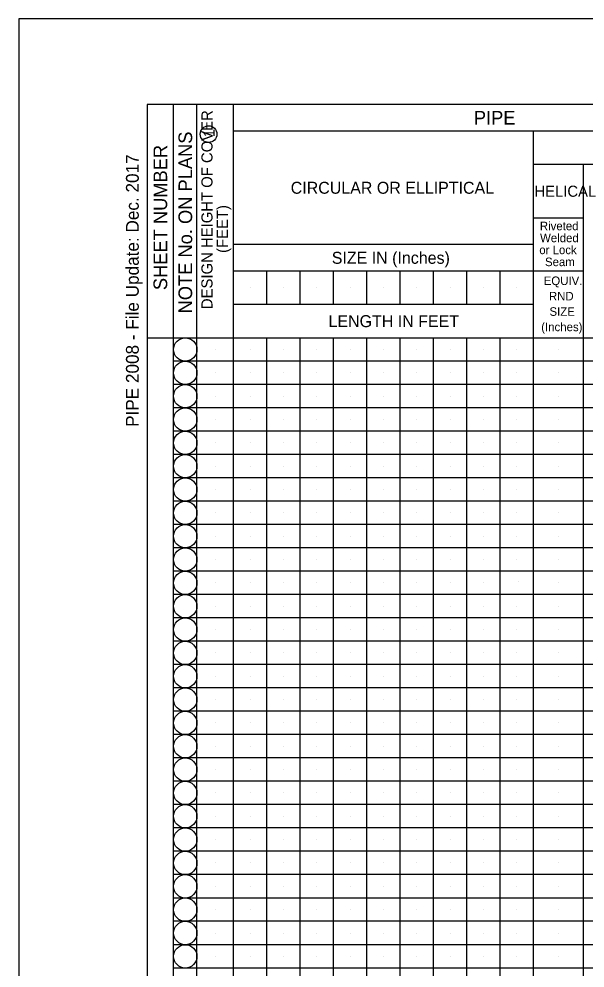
# Model space of a CAD drawing. Extents: x -1700 to 0, y 0 to 1100.
# Drawn here: x -1700 to -1368, y 545 to 1100 of the extents above; entities that cross this region are included whole.
import ezdxf

# ---------------------------------------------------------------- set-up
doc = ezdxf.new("R2010")
doc.units = 0
for name, color, linetype in [('#plot_shape', 7, 'Continuous'), ('P_ODOT_PLAN_Border', 7, 'Continuous'), ('P_ODOT_PLAN_General', 7, 'Continuous'), ('P_RDWY_PLAN_NotesTx', 7, 'Continuous')]:
    doc.layers.add(name, color=color, linetype=linetype)

msp = doc.modelspace()

# ---------------------------------------------------------------- linework, layer by layer
at = {"layer": '#plot_shape'}
msp.add_lwpolyline([(-1700, 0), (0, 0), (0, 1100), (-1700, 1100)], close=True, dxfattribs=at)
at = {"layer": 'P_ODOT_PLAN_Border'}
msp.add_lwpolyline([(-1625, 50), (-25, 50), (-25, 1050), (-1625, 1050)], close=True, dxfattribs=at)
at = {"layer": 'P_ODOT_PLAN_General'}
for p, q in [((-1609.39, 312.45), (-1609.39, 1050)), ((-1595.73, 312.45), (-1595.73, 1050)), ((-1574.27, 312.45), (-1574.27, 1050)), ((-1271.83, 1034.39), (-1574.27, 1034.39)), ((-1398.66, 312.45), (-1398.66, 1034.39)), ((-1271.83, 1014.88), (-1398.66, 1014.88)), ((-1369.39, 312.45), (-1369.39, 1014.88)), ((-1398.66, 983.66), (-1369.39, 983.66)), ((-1398.66, 968.05), (-1574.27, 968.05)), ((-1369.39, 952.44), (-1574.27, 952.44)), ((-1554.76, 932.93), (-1554.76, 952.44)), ((-1535.24, 932.93), (-1535.24, 952.44)), ((-1515.73, 932.93), (-1515.73, 952.44)), ((-1496.22, 932.93), (-1496.22, 952.44)), ((-1476.71, 932.93), (-1476.71, 952.44)), ((-1457.2, 932.93), (-1457.2, 952.44)), ((-1437.68, 932.93), (-1437.68, 952.44)), ((-1418.17, 932.93), (-1418.17, 952.44)), ((-1564.51, 942.68), (-1564.51, 942.68)), ((-1545, 942.68), (-1545, 942.68)), ((-1525.49, 942.68), (-1525.49, 942.68)), ((-1505.98, 942.68), (-1505.98, 942.68)), ((-1486.46, 942.68), (-1486.46, 942.68)), ((-1466.95, 942.68), (-1466.95, 942.68)), ((-1447.44, 942.68), (-1447.44, 942.68)), ((-1427.93, 942.68), (-1427.93, 942.68)), ((-1408.42, 942.68), (-1408.42, 942.68)), ((-1398.66, 932.93), (-1574.27, 932.93)), ((-1625, 913.42), (-1271.83, 913.42)), ((-1554.76, 312.45), (-1554.76, 913.42)), ((-1535.24, 312.45), (-1535.24, 913.42)), ((-1515.73, 312.45), (-1515.73, 913.42)), ((-1496.22, 312.45), (-1496.22, 913.42)), ((-1476.71, 312.45), (-1476.71, 913.42)), ((-1457.2, 312.45), (-1457.2, 913.42)), ((-1437.68, 312.45), (-1437.68, 913.42)), ((-1418.17, 312.45), (-1418.17, 913.42)), ((-1585, 906.59), (-1585, 906.59)), ((-1564.51, 906.59), (-1564.51, 906.59)), ((-1545, 906.59), (-1545, 906.59)), ((-1525.49, 906.59), (-1525.49, 906.59)), ((-1505.89, 906.75), (-1505.89, 906.75)), ((-1486.46, 906.59), (-1486.46, 906.59)), ((-1466.95, 906.59), (-1466.95, 906.59)), ((-1447.44, 906.59), (-1447.44, 906.59)), ((-1427.93, 906.59), (-1427.93, 906.59)), ((-1408.42, 906.59), (-1408.42, 906.59)), ((-1384.03, 906.59), (-1384.03, 906.59)), ((-1398.66, 899.76), (-1609.39, 899.76)), ((-1088.42, 899.76), (-1398.66, 899.76)), ((-1585, 892.93), (-1585, 892.93)), ((-1564.51, 892.93), (-1564.51, 892.93)), ((-1545, 892.93), (-1545, 892.93)), ((-1525.49, 892.93), (-1525.49, 892.93)), ((-1505.98, 892.93), (-1505.98, 892.93)), ((-1486.46, 892.93), (-1486.46, 892.93)), ((-1466.95, 892.93), (-1466.95, 892.93)), ((-1447.44, 892.93), (-1447.44, 892.93)), ((-1427.93, 892.93), (-1427.93, 892.93)), ((-1408.42, 892.93), (-1408.42, 892.93)), ((-1384.03, 892.93), (-1384.03, 892.93)), ((-1398.66, 886.1), (-1609.39, 886.1)), ((-1088.42, 886.1), (-1398.66, 886.1)), ((-1585, 879.27), (-1585, 879.27)), ((-1564.51, 879.27), (-1564.51, 879.27)), ((-1545, 879.27), (-1545, 879.27)), ((-1525.49, 879.27), (-1525.49, 879.27)), ((-1505.98, 879.27), (-1505.98, 879.27)), ((-1486.46, 879.27), (-1486.46, 879.27)), ((-1466.95, 879.27), (-1466.95, 879.27)), ((-1447.44, 879.27), (-1447.44, 879.27)), ((-1427.93, 879.27), (-1427.93, 879.27)), ((-1408.42, 879.27), (-1408.42, 879.27)), ((-1384.03, 879.27), (-1384.03, 879.27)), ((-1398.66, 872.44), (-1609.39, 872.44)), ((-1088.42, 872.44), (-1398.66, 872.44)), ((-1585, 865.61), (-1585, 865.61)), ((-1564.51, 865.61), (-1564.51, 865.61)), ((-1545, 865.61), (-1545, 865.61)), ((-1525.49, 865.61), (-1525.49, 865.61)), ((-1505.98, 865.61), (-1505.98, 865.61)), ((-1486.46, 865.61), (-1486.46, 865.61)), ((-1466.95, 865.61), (-1466.95, 865.61)), ((-1447.44, 865.61), (-1447.44, 865.61)), ((-1427.93, 865.61), (-1427.93, 865.61)), ((-1408.42, 865.61), (-1408.42, 865.61)), ((-1384.03, 865.61), (-1384.03, 865.61)), ((-1398.66, 858.78), (-1609.39, 858.78)), ((-1088.42, 858.78), (-1398.66, 858.78)), ((-1585, 851.95), (-1585, 851.95)), ((-1564.51, 851.95), (-1564.51, 851.95)), ((-1545, 851.95), (-1545, 851.95)), ((-1525.49, 851.95), (-1525.49, 851.95)), ((-1505.98, 851.95), (-1505.98, 851.95)), ((-1486.46, 851.95), (-1486.46, 851.95)), ((-1466.95, 851.95), (-1466.95, 851.95)), ((-1447.44, 851.95), (-1447.44, 851.95)), ((-1427.93, 851.95), (-1427.93, 851.95)), ((-1408.42, 851.95), (-1408.42, 851.95)), ((-1384.03, 851.95), (-1384.03, 851.95)), ((-1398.66, 845.12), (-1609.39, 845.12)), ((-1088.42, 845.12), (-1398.66, 845.12)), ((-1585, 838.29), (-1585, 838.29)), ((-1564.51, 838.29), (-1564.51, 838.29)), ((-1545, 838.29), (-1545, 838.29)), ((-1525.49, 838.29), (-1525.49, 838.29)), ((-1505.98, 838.29), (-1505.98, 838.29)), ((-1486.46, 838.29), (-1486.46, 838.29)), ((-1466.95, 838.29), (-1466.95, 838.29)), ((-1447.44, 838.29), (-1447.44, 838.29)), ((-1427.93, 838.29), (-1427.93, 838.29)), ((-1408.42, 838.29), (-1408.42, 838.29)), ((-1384.03, 838.29), (-1384.03, 838.29)), ((-1398.66, 831.47), (-1609.39, 831.47)), ((-1088.42, 831.47), (-1398.66, 831.47)), ((-1585, 824.64), (-1585, 824.64)), ((-1564.51, 824.64), (-1564.51, 824.64)), ((-1545, 824.64), (-1545, 824.64)), ((-1525.49, 824.64), (-1525.49, 824.64)), ((-1505.98, 824.64), (-1505.98, 824.64)), ((-1486.46, 824.64), (-1486.46, 824.64)), ((-1466.95, 824.64), (-1466.95, 824.64)), ((-1447.44, 824.64), (-1447.44, 824.64)), ((-1427.93, 824.64), (-1427.93, 824.64)), ((-1408.42, 824.64), (-1408.42, 824.64)), ((-1384.03, 824.64), (-1384.03, 824.64)), ((-1398.66, 817.81), (-1609.39, 817.81)), ((-1088.42, 817.81), (-1398.66, 817.81)), ((-1585, 810.98), (-1585, 810.98)), ((-1564.51, 810.98), (-1564.51, 810.98)), ((-1545, 810.98), (-1545, 810.98)), ((-1525.49, 810.98), (-1525.49, 810.98)), ((-1505.98, 810.98), (-1505.98, 810.98)), ((-1486.46, 810.98), (-1486.46, 810.98)), ((-1466.95, 810.98), (-1466.95, 810.98)), ((-1447.44, 810.98), (-1447.44, 810.98)), ((-1427.93, 810.98), (-1427.93, 810.98)), ((-1408.42, 810.98), (-1408.42, 810.98)), ((-1384.03, 810.98), (-1384.03, 810.98)), ((-1398.66, 804.15), (-1609.39, 804.15)), ((-1088.42, 804.15), (-1398.66, 804.15)), ((-1585, 797.32), (-1585, 797.32)), ((-1564.51, 797.32), (-1564.51, 797.32)), ((-1545, 797.32), (-1545, 797.32)), ((-1525.49, 797.32), (-1525.49, 797.32)), ((-1505.98, 797.32), (-1505.98, 797.32)), ((-1486.46, 797.32), (-1486.46, 797.32)), ((-1466.95, 797.32), (-1466.95, 797.32)), ((-1447.44, 797.32), (-1447.44, 797.32)), ((-1427.93, 797.32), (-1427.93, 797.32)), ((-1408.42, 797.32), (-1408.42, 797.32)), ((-1384.03, 797.32), (-1384.03, 797.32)), ((-1398.66, 790.49), (-1609.39, 790.49)), ((-1088.42, 790.49), (-1398.66, 790.49)), ((-1585, 783.66), (-1585, 783.66)), ((-1564.51, 783.66), (-1564.51, 783.66)), ((-1545, 783.66), (-1545, 783.66)), ((-1525.49, 783.66), (-1525.49, 783.66)), ((-1505.98, 783.66), (-1505.98, 783.66)), ((-1486.46, 783.66), (-1486.46, 783.66)), ((-1466.95, 783.66), (-1466.95, 783.66)), ((-1447.44, 783.66), (-1447.44, 783.66)), ((-1427.66, 783.6), (-1427.66, 783.6)), ((-1408.42, 783.66), (-1408.42, 783.66)), ((-1384.03, 783.66), (-1384.03, 783.66)), ((-1398.66, 776.83), (-1609.39, 776.83)), ((-1088.42, 776.83), (-1398.66, 776.83)), ((-1585, 770), (-1585, 770)), ((-1564.51, 770), (-1564.51, 770)), ((-1545, 770), (-1545, 770)), ((-1525.49, 770), (-1525.49, 770)), ((-1505.98, 770), (-1505.98, 770)), ((-1486.46, 770), (-1486.46, 770)), ((-1466.95, 770), (-1466.95, 770)), ((-1447.44, 770), (-1447.44, 770)), ((-1427.93, 770), (-1427.93, 770)), ((-1407.63, 770.56), (-1407.63, 770.56)), ((-1384.03, 770), (-1384.03, 770)), ((-1398.66, 763.17), (-1609.39, 763.17)), ((-1088.42, 763.17), (-1398.66, 763.17)), ((-1585, 756.34), (-1585, 756.34)), ((-1564.51, 756.34), (-1564.51, 756.34)), ((-1545, 756.34), (-1545, 756.34)), ((-1525.49, 756.34), (-1525.49, 756.34)), ((-1505.98, 756.34), (-1505.98, 756.34)), ((-1486.46, 756.34), (-1486.46, 756.34)), ((-1466.95, 756.34), (-1466.95, 756.34)), ((-1447.44, 756.34), (-1447.44, 756.34)), ((-1427.93, 756.34), (-1427.93, 756.34)), ((-1408.42, 756.34), (-1408.42, 756.34)), ((-1384.03, 756.34), (-1384.03, 756.34)), ((-1398.66, 749.52), (-1609.39, 749.52)), ((-1088.42, 749.52), (-1398.66, 749.52)), ((-1585, 742.69), (-1585, 742.69)), ((-1564.51, 742.69), (-1564.51, 742.69)), ((-1545, 742.69), (-1545, 742.69)), ((-1525.49, 742.69), (-1525.49, 742.69)), ((-1505.98, 742.69), (-1505.98, 742.69)), ((-1486.46, 742.69), (-1486.46, 742.69)), ((-1466.95, 742.69), (-1466.95, 742.69)), ((-1447.44, 742.69), (-1447.44, 742.69)), ((-1427.93, 742.69), (-1427.93, 742.69)), ((-1408.42, 742.69), (-1408.42, 742.69)), ((-1384.03, 742.69), (-1384.03, 742.69)), ((-1398.66, 735.86), (-1609.39, 735.86)), ((-1088.42, 735.86), (-1398.66, 735.86)), ((-1585, 729.03), (-1585, 729.03)), ((-1564.51, 729.03), (-1564.51, 729.03)), ((-1545, 729.03), (-1545, 729.03)), ((-1525.49, 729.03), (-1525.49, 729.03)), ((-1505.98, 729.03), (-1505.98, 729.03)), ((-1486.46, 729.03), (-1486.46, 729.03)), ((-1466.95, 729.03), (-1466.95, 729.03)), ((-1447.44, 729.03), (-1447.44, 729.03)), ((-1427.93, 729.03), (-1427.93, 729.03)), ((-1408.42, 729.03), (-1408.42, 729.03)), ((-1384.03, 729.03), (-1384.03, 729.03)), ((-1398.66, 722.2), (-1609.39, 722.2)), ((-1088.42, 722.2), (-1398.66, 722.2)), ((-1585, 715.37), (-1585, 715.37)), ((-1564.51, 715.37), (-1564.51, 715.37)), ((-1545, 715.37), (-1545, 715.37)), ((-1525.49, 715.37), (-1525.49, 715.37)), ((-1505.98, 715.37), (-1505.98, 715.37)), ((-1486.46, 715.37), (-1486.46, 715.37)), ((-1466.95, 715.37), (-1466.95, 715.37)), ((-1447.44, 715.37), (-1447.44, 715.37)), ((-1427.93, 715.37), (-1427.93, 715.37)), ((-1408.42, 715.37), (-1408.42, 715.37)), ((-1384.03, 715.37), (-1384.03, 715.37)), ((-1398.66, 708.54), (-1609.39, 708.54)), ((-1088.42, 708.54), (-1398.66, 708.54)), ((-1585, 701.71), (-1585, 701.71)), ((-1564.51, 701.71), (-1564.51, 701.71)), ((-1545, 701.71), (-1545, 701.71)), ((-1525.49, 701.71), (-1525.49, 701.71)), ((-1505.98, 701.71), (-1505.98, 701.71)), ((-1486.46, 701.71), (-1486.46, 701.71)), ((-1466.95, 701.71), (-1466.95, 701.71)), ((-1447.44, 701.71), (-1447.44, 701.71)), ((-1427.93, 701.71), (-1427.93, 701.71)), ((-1408.42, 701.71), (-1408.42, 701.71)), ((-1384.03, 701.71), (-1384.03, 701.71)), ((-1398.66, 694.88), (-1609.39, 694.88)), ((-1088.42, 694.88), (-1398.66, 694.88)), ((-1585, 688.05), (-1585, 688.05)), ((-1564.51, 688.05), (-1564.51, 688.05)), ((-1545, 688.05), (-1545, 688.05)), ((-1525.49, 688.05), (-1525.49, 688.05)), ((-1505.98, 688.05), (-1505.98, 688.05)), ((-1486.46, 688.05), (-1486.46, 688.05)), ((-1466.95, 688.05), (-1466.95, 688.05)), ((-1447.44, 688.05), (-1447.44, 688.05)), ((-1427.93, 688.05), (-1427.93, 688.05)), ((-1408.42, 688.05), (-1408.42, 688.05)), ((-1384.03, 688.05), (-1384.03, 688.05)), ((-1398.66, 681.22), (-1609.39, 681.22)), ((-1088.42, 681.22), (-1398.66, 681.22)), ((-1585, 674.39), (-1585, 674.39)), ((-1564.51, 674.39), (-1564.51, 674.39)), ((-1545, 674.39), (-1545, 674.39)), ((-1525.49, 674.39), (-1525.49, 674.39)), ((-1505.98, 674.39), (-1505.98, 674.39)), ((-1486.46, 674.39), (-1486.46, 674.39)), ((-1466.95, 674.39), (-1466.95, 674.39)), ((-1447.44, 674.39), (-1447.44, 674.39)), ((-1427.93, 674.39), (-1427.93, 674.39)), ((-1408.42, 674.39), (-1408.42, 674.39)), ((-1384.03, 674.39), (-1384.03, 674.39)), ((-1398.66, 667.56), (-1609.39, 667.56)), ((-1088.42, 667.56), (-1398.66, 667.56)), ((-1585, 660.74), (-1585, 660.74)), ((-1564.51, 660.74), (-1564.51, 660.74)), ((-1545, 660.74), (-1545, 660.74)), ((-1525.49, 660.74), (-1525.49, 660.74)), ((-1505.98, 660.74), (-1505.98, 660.74)), ((-1486.46, 660.74), (-1486.46, 660.74)), ((-1466.95, 660.74), (-1466.95, 660.74)), ((-1447.44, 660.74), (-1447.44, 660.74)), ((-1427.93, 660.74), (-1427.93, 660.74)), ((-1408.42, 660.74), (-1408.42, 660.74)), ((-1384.03, 660.74), (-1384.03, 660.74)), ((-1398.66, 653.91), (-1609.39, 653.91)), ((-1595.73, 640.25), (-1595.73, 653.91)), ((-1088.42, 653.91), (-1398.66, 653.91)), ((-1585, 647.08), (-1585, 647.08)), ((-1564.51, 647.08), (-1564.51, 647.08)), ((-1545, 647.08), (-1545, 647.08)), ((-1525.49, 647.08), (-1525.49, 647.08)), ((-1505.98, 647.08), (-1505.98, 647.08)), ((-1486.46, 647.08), (-1486.46, 647.08)), ((-1466.95, 647.08), (-1466.95, 647.08)), ((-1447.44, 647.08), (-1447.44, 647.08)), ((-1427.93, 647.08), (-1427.93, 647.08)), ((-1408.42, 647.08), (-1408.42, 647.08)), ((-1384.03, 647.08), (-1384.03, 647.08)), ((-1398.66, 640.25), (-1609.39, 640.25)), ((-1088.42, 640.25), (-1398.66, 640.25)), ((-1585, 633.42), (-1585, 633.42)), ((-1564.51, 633.42), (-1564.51, 633.42)), ((-1545, 633.42), (-1545, 633.42)), ((-1525.49, 633.42), (-1525.49, 633.42)), ((-1505.98, 633.42), (-1505.98, 633.42)), ((-1486.46, 633.42), (-1486.46, 633.42)), ((-1466.95, 633.42), (-1466.95, 633.42)), ((-1447.44, 633.42), (-1447.44, 633.42)), ((-1427.93, 633.42), (-1427.93, 633.42)), ((-1408.42, 633.42), (-1408.42, 633.42)), ((-1384.03, 633.42), (-1384.03, 633.42)), ((-1398.66, 626.59), (-1609.39, 626.59)), ((-1088.42, 626.59), (-1398.66, 626.59)), ((-1585, 619.76), (-1585, 619.76)), ((-1564.51, 619.76), (-1564.51, 619.76)), ((-1545, 619.76), (-1545, 619.76)), ((-1525.49, 619.76), (-1525.49, 619.76)), ((-1505.98, 619.76), (-1505.98, 619.76)), ((-1486.46, 619.76), (-1486.46, 619.76)), ((-1466.95, 619.76), (-1466.95, 619.76)), ((-1447.44, 619.76), (-1447.44, 619.76)), ((-1427.93, 619.76), (-1427.93, 619.76)), ((-1408.42, 619.76), (-1408.42, 619.76)), ((-1384.03, 619.76), (-1384.03, 619.76)), ((-1398.66, 612.93), (-1609.39, 612.93)), ((-1088.42, 612.93), (-1398.66, 612.93)), ((-1585, 606.1), (-1585, 606.1)), ((-1564.51, 606.1), (-1564.51, 606.1)), ((-1545, 606.1), (-1545, 606.1)), ((-1525.49, 606.1), (-1525.49, 606.1)), ((-1505.98, 606.1), (-1505.98, 606.1)), ((-1486.46, 606.1), (-1486.46, 606.1)), ((-1466.95, 606.1), (-1466.95, 606.1)), ((-1447.44, 606.1), (-1447.44, 606.1)), ((-1427.93, 606.1), (-1427.93, 606.1)), ((-1408.42, 606.1), (-1408.42, 606.1)), ((-1384.03, 606.1), (-1384.03, 606.1)), ((-1398.66, 599.27), (-1609.39, 599.27)), ((-1088.42, 599.27), (-1398.66, 599.27)), ((-1585, 592.44), (-1585, 592.44)), ((-1564.51, 592.44), (-1564.51, 592.44)), ((-1545, 592.44), (-1545, 592.44)), ((-1525.49, 592.44), (-1525.49, 592.44)), ((-1505.98, 592.44), (-1505.98, 592.44)), ((-1486.46, 592.44), (-1486.46, 592.44)), ((-1466.95, 592.44), (-1466.95, 592.44)), ((-1447.44, 592.44), (-1447.44, 592.44)), ((-1427.93, 592.44), (-1427.93, 592.44)), ((-1408.42, 592.44), (-1408.42, 592.44)), ((-1384.03, 592.44), (-1384.03, 592.44)), ((-1398.66, 585.61), (-1609.39, 585.61)), ((-1088.42, 585.61), (-1398.66, 585.61)), ((-1585, 578.79), (-1585, 578.79)), ((-1564.51, 578.79), (-1564.51, 578.79)), ((-1545, 578.79), (-1545, 578.79)), ((-1525.49, 578.79), (-1525.49, 578.79)), ((-1505.98, 578.79), (-1505.98, 578.79)), ((-1486.46, 578.79), (-1486.46, 578.79)), ((-1466.95, 578.79), (-1466.95, 578.79)), ((-1447.44, 578.79), (-1447.44, 578.79)), ((-1427.93, 578.79), (-1427.93, 578.79)), ((-1408.42, 578.79), (-1408.42, 578.79)), ((-1384.03, 578.79), (-1384.03, 578.79)), ((-1398.66, 571.96), (-1609.39, 571.96)), ((-1088.42, 571.96), (-1398.66, 571.96)), ((-1585, 565.13), (-1585, 565.13)), ((-1564.51, 565.13), (-1564.51, 565.13)), ((-1545, 565.13), (-1545, 565.13)), ((-1525.49, 565.13), (-1525.49, 565.13)), ((-1505.98, 565.13), (-1505.98, 565.13)), ((-1486.46, 565.13), (-1486.46, 565.13)), ((-1466.95, 565.13), (-1466.95, 565.13)), ((-1447.44, 565.13), (-1447.44, 565.13)), ((-1427.93, 565.13), (-1427.93, 565.13)), ((-1408.42, 565.13), (-1408.42, 565.13)), ((-1384.03, 565.13), (-1384.03, 565.13)), ((-1398.66, 558.3), (-1609.39, 558.3)), ((-1088.42, 558.3), (-1398.66, 558.3)), ((-1585, 551.47), (-1585, 551.47)), ((-1564.51, 551.47), (-1564.51, 551.47)), ((-1545, 551.47), (-1545, 551.47)), ((-1525.49, 551.47), (-1525.49, 551.47)), ((-1505.98, 551.47), (-1505.98, 551.47)), ((-1486.46, 551.47), (-1486.46, 551.47)), ((-1466.95, 551.47), (-1466.95, 551.47)), ((-1447.44, 551.47), (-1447.44, 551.47)), ((-1427.93, 551.47), (-1427.93, 551.47)), ((-1408.42, 551.47), (-1408.42, 551.47)), ((-1384.03, 551.47), (-1384.03, 551.47)), ((-1398.66, 544.64), (-1609.39, 544.64)), ((-1088.42, 544.64), (-1398.66, 544.64))]:
    msp.add_line(p, q, dxfattribs=at)
for centre in [(-1602.56, 906.59), (-1602.56, 892.93), (-1602.56, 879.27), (-1602.56, 865.61), (-1602.56, 851.95), (-1602.56, 838.29), (-1602.56, 824.64), (-1602.56, 810.98), (-1602.56, 797.32), (-1602.56, 783.66), (-1602.56, 770), (-1602.56, 756.34), (-1602.56, 742.69), (-1602.56, 729.03), (-1602.56, 715.37), (-1602.56, 701.71), (-1602.56, 688.05), (-1602.56, 674.39), (-1602.56, 660.74), (-1602.56, 647.08), (-1602.56, 633.42), (-1602.56, 619.76), (-1602.56, 606.1), (-1602.56, 592.44), (-1602.56, 578.79), (-1602.56, 565.13), (-1602.56, 551.47)]:
    msp.add_circle(centre, 6.83, dxfattribs=at)
at = {"layer": 'P_RDWY_PLAN_NotesTx'}
msp.add_circle((-1588.9, 1032.63), 4.88, dxfattribs=at)

# ---------------------------------------------------------------- texts
for s, height, p in [('DESIGN HEIGHT OF COVER', 6.5, (-1586.63, 930.22)), ('NOTE No. ON PLANS', 8, (-1598.56, 927.71)), ('1', 6.5, (-1585.41, 1030.8)), ('SHEET NUMBER', 8, (-1613.19, 941.32)), ('PIPE 2008 - File Update: Dec. 2017', 7.5, (-1629.83, 861.31)), ('(FEET)', 6.5, (-1577.61, 963.1))]:
    msp.add_text(s, height=height, rotation=90, dxfattribs=at).set_placement(p)
for s, height, p in [('PIPE', 8, (-1433.54, 1038.2)), ('CIRCULAR OR ELLIPTICAL', 7, (-1540.82, 997.72)), ('HELICAL', 6.5, (-1398.1, 995.96)), ('Riveted', 5, (-1394.9, 976.37)), ('Welded', 5, (-1394.78, 969.37)), ('or Lock', 5, (-1395.22, 962.37)), ('SIZE IN (Inches)', 7, (-1516.78, 956.74)), ('Seam', 5, (-1391.88, 955.37)), ('EQUIV.', 5, (-1392.63, 944.3)), ('RND', 5, (-1389.58, 935.3)), ('SIZE', 5, (-1389.25, 926.3)), ('LENGTH IN FEET', 7, (-1518.68, 919.67)), ('(Inches)', 5, (-1394.09, 917.3))]:
    msp.add_text(s, height=height, dxfattribs=at).set_placement(p)

doc.saveas('drawing.dxf')
